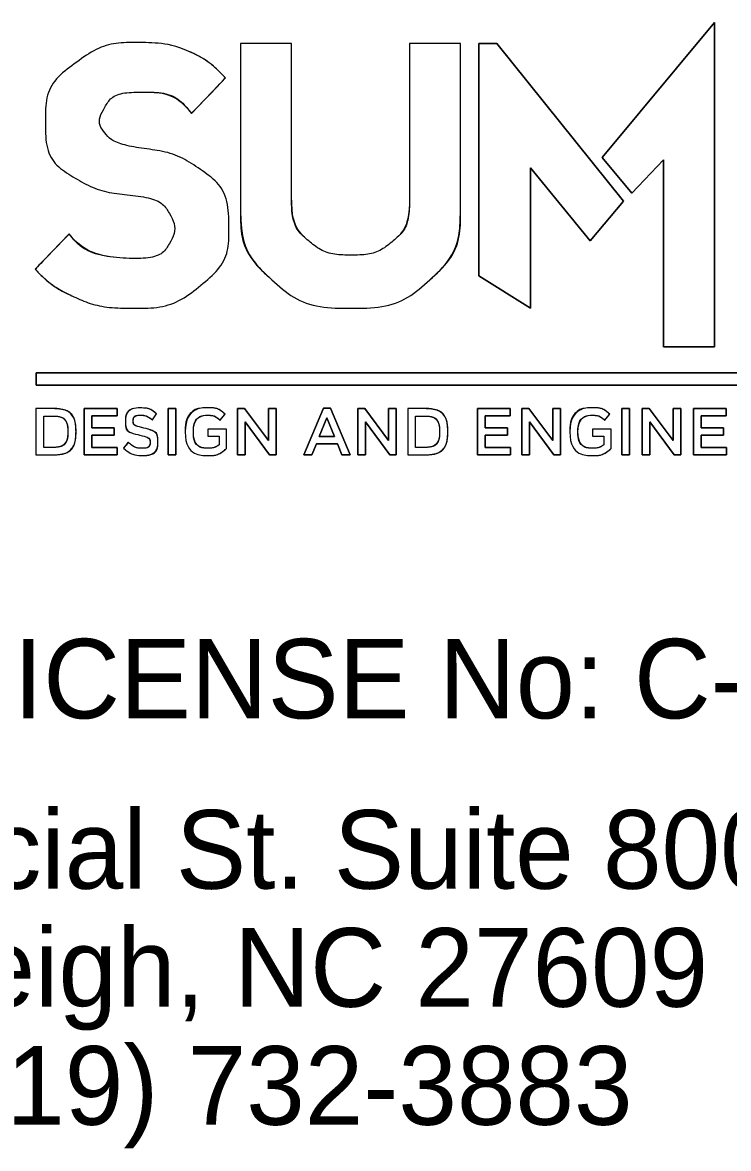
# Model space of a CAD drawing. Extents: x 1676398 to 1678098, y 1329391 to 1330491.
# Drawn here: x 1678017.5 to 1678052.2, y 1330290.2 to 1330345.6 of the extents above; entities that cross this region are included whole.
import ezdxf

# ---------------------------------------------------------------- set-up
doc = ezdxf.new("R2010")
doc.units = 0
doc.layers.add('Sheet Plan CELL', color=7, linetype='Continuous')

msp = doc.modelspace()

# ---------------------------------------------------------------- linework, layer by layer
at = {"layer": 'Sheet Plan CELL'}
for p, q in [((1678025.855, 1330341.09), (1678027.526, 1330342.832)), ((1678019.841, 1330335.167), (1678018.17, 1330333.425)), ((1678022.603, 1330325.946), (1678022.603, 1330325.94)), ((1678022.986, 1330325.975), (1678022.986, 1330325.982)), ((1678023.932, 1330326.018), (1678024.138, 1330326.319)), ((1678027.262, 1330326.001), (1678027.504, 1330326.303)), ((1678046.168, 1330326.001), (1678046.411, 1330326.303)), ((1678019.775, 1330325.437), (1678019.775, 1330325.43)), ((1678020.177, 1330325.437), (1678020.177, 1330325.443)), ((1678025.544, 1330325.437), (1678025.544, 1330325.43)), ((1678025.945, 1330325.437), (1678025.945, 1330325.443)), ((1678038.049, 1330325.437), (1678038.049, 1330325.43)), ((1678038.451, 1330325.437), (1678038.451, 1330325.443)), ((1678044.45, 1330325.437), (1678044.45, 1330325.43)), ((1678044.851, 1330325.437), (1678044.851, 1330325.443)), ((1678022.746, 1330324.918), (1678022.516, 1330324.632)), ((1678023.82, 1330324.914), (1678023.82, 1330324.908)), ((1678024.203, 1330324.947), (1678024.203, 1330324.953))]:
    msp.add_line(p, q, dxfattribs=at)
for points in [[(1678051.569, 1330345.559), (1678051.569, 1330329.619), (1678049.058, 1330329.619), (1678049.058, 1330338.813), (1678047.503, 1330337.167), (1678046.041, 1330338.914), (1678051.569, 1330345.559)], [(1678046.041, 1330338.914), (1678047.503, 1330337.167), (1678049.058, 1330338.813), (1678049.058, 1330329.619), (1678051.569, 1330329.619), (1678051.569, 1330345.559), (1678046.041, 1330338.914)], [(1678030.773, 1330336.997), (1678030.773, 1330344.521), (1678028.262, 1330344.521), (1678028.262, 1330336.3)], [(1678039.079, 1330336.3), (1678039.079, 1330344.521), (1678036.567, 1330344.521), (1678036.567, 1330336.997)], [(1678040.865, 1330344.521), (1678047.096, 1330336.768), (1678045.45, 1330334.816), (1678042.511, 1330338.409), (1678042.511, 1330331.506), (1678039.98, 1330333.11), (1678039.98, 1330344.521), (1678040.865, 1330344.521)], [(1678039.98, 1330344.521), (1678039.98, 1330333.11), (1678042.511, 1330331.506), (1678042.511, 1330338.409), (1678045.45, 1330334.816), (1678047.096, 1330336.768), (1678040.865, 1330344.521), (1678039.98, 1330344.521)], [(1678079.061, 1330327.731), (1678018.218, 1330327.731), (1678018.218, 1330328.335), (1678079.061, 1330328.335), (1678079.061, 1330327.731)], [(1678079.061, 1330328.335), (1678018.218, 1330328.335), (1678018.218, 1330327.731), (1678079.061, 1330327.731), (1678079.061, 1330328.335)], [(1678019.019, 1330326.572), (1678018.207, 1330326.572), (1678018.207, 1330324.301), (1678019.019, 1330324.301)], [(1678020.578, 1330326.572), (1678022.193, 1330326.572), (1678022.193, 1330326.215), (1678020.96, 1330326.215), (1678020.96, 1330325.625), (1678022.053, 1330325.625), (1678022.053, 1330325.268), (1678020.96, 1330325.268), (1678020.96, 1330324.658), (1678022.208, 1330324.658), (1678022.208, 1330324.301), (1678020.578, 1330324.301), (1678020.578, 1330326.572)], [(1678020.578, 1330324.301), (1678022.208, 1330324.301), (1678022.208, 1330324.658), (1678020.96, 1330324.658), (1678020.96, 1330325.268), (1678022.053, 1330325.268), (1678022.053, 1330325.625), (1678020.96, 1330325.625), (1678020.96, 1330326.215), (1678022.193, 1330326.215), (1678022.193, 1330326.572), (1678020.578, 1330326.572), (1678020.578, 1330324.301)], [(1678024.706, 1330326.572), (1678025.089, 1330326.572), (1678025.089, 1330324.301), (1678024.706, 1330324.301), (1678024.706, 1330326.572)], [(1678024.706, 1330324.301), (1678025.089, 1330324.301), (1678025.089, 1330326.572), (1678024.706, 1330326.572), (1678024.706, 1330324.301)], [(1678028.111, 1330326.572), (1678028.465, 1330326.572), (1678029.633, 1330325.002), (1678029.633, 1330326.572), (1678030.009, 1330326.572), (1678030.009, 1330324.301), (1678029.688, 1330324.301), (1678028.487, 1330325.917), (1678028.487, 1330324.301), (1678028.111, 1330324.301), (1678028.111, 1330326.572)], [(1678028.111, 1330324.301), (1678028.487, 1330324.301), (1678028.487, 1330325.917), (1678029.688, 1330324.301), (1678030.009, 1330324.301), (1678030.009, 1330326.572), (1678029.633, 1330326.572), (1678029.633, 1330325.002), (1678028.465, 1330326.572), (1678028.111, 1330326.572), (1678028.111, 1330324.301)], [(1678032.336, 1330326.589), (1678032.691, 1330326.589), (1678033.65, 1330324.301), (1678033.245, 1330324.301), (1678033.024, 1330324.849), (1678031.994, 1330324.849), (1678031.77, 1330324.301), (1678031.378, 1330324.301), (1678032.336, 1330326.589)], [(1678031.378, 1330324.301), (1678031.77, 1330324.301), (1678031.994, 1330324.849), (1678033.024, 1330324.849), (1678033.245, 1330324.301), (1678033.65, 1330324.301), (1678032.691, 1330326.589), (1678032.336, 1330326.589), (1678031.378, 1330324.301)], [(1678034.023, 1330326.572), (1678034.378, 1330326.572), (1678035.544, 1330325.002), (1678035.544, 1330326.572), (1678035.921, 1330326.572), (1678035.921, 1330324.301), (1678035.601, 1330324.301), (1678034.399, 1330325.917), (1678034.399, 1330324.301), (1678034.023, 1330324.301), (1678034.023, 1330326.572)], [(1678034.023, 1330324.301), (1678034.399, 1330324.301), (1678034.399, 1330325.917), (1678035.601, 1330324.301), (1678035.921, 1330324.301), (1678035.921, 1330326.572), (1678035.544, 1330326.572), (1678035.544, 1330325.002), (1678034.378, 1330326.572), (1678034.023, 1330326.572), (1678034.023, 1330324.301)], [(1678037.293, 1330326.572), (1678036.481, 1330326.572), (1678036.481, 1330324.301), (1678037.293, 1330324.301)], [(1678039.91, 1330326.572), (1678041.525, 1330326.572), (1678041.525, 1330326.215), (1678040.293, 1330326.215), (1678040.293, 1330325.625), (1678041.385, 1330325.625), (1678041.385, 1330325.268), (1678040.293, 1330325.268), (1678040.293, 1330324.658), (1678041.541, 1330324.658), (1678041.541, 1330324.301), (1678039.91, 1330324.301), (1678039.91, 1330326.572)], [(1678039.91, 1330324.301), (1678041.541, 1330324.301), (1678041.541, 1330324.658), (1678040.293, 1330324.658), (1678040.293, 1330325.268), (1678041.385, 1330325.268), (1678041.385, 1330325.625), (1678040.293, 1330325.625), (1678040.293, 1330326.215), (1678041.525, 1330326.215), (1678041.525, 1330326.572), (1678039.91, 1330326.572), (1678039.91, 1330324.301)], [(1678042.088, 1330326.572), (1678042.443, 1330326.572), (1678043.61, 1330325.002), (1678043.61, 1330326.572), (1678043.986, 1330326.572), (1678043.986, 1330324.301), (1678043.666, 1330324.301), (1678042.464, 1330325.917), (1678042.464, 1330324.301), (1678042.088, 1330324.301), (1678042.088, 1330326.572)], [(1678042.088, 1330324.301), (1678042.464, 1330324.301), (1678042.464, 1330325.917), (1678043.666, 1330324.301), (1678043.986, 1330324.301), (1678043.986, 1330326.572), (1678043.61, 1330326.572), (1678043.61, 1330325.002), (1678042.443, 1330326.572), (1678042.088, 1330326.572), (1678042.088, 1330324.301)], [(1678047.007, 1330326.572), (1678047.39, 1330326.572), (1678047.39, 1330324.301), (1678047.007, 1330324.301), (1678047.007, 1330326.572)], [(1678047.007, 1330324.301), (1678047.39, 1330324.301), (1678047.39, 1330326.572), (1678047.007, 1330326.572), (1678047.007, 1330324.301)], [(1678048.003, 1330326.572), (1678048.358, 1330326.572), (1678049.525, 1330325.002), (1678049.525, 1330326.572), (1678049.902, 1330326.572), (1678049.902, 1330324.301), (1678049.581, 1330324.301), (1678048.38, 1330325.917), (1678048.38, 1330324.301), (1678048.003, 1330324.301), (1678048.003, 1330326.572)], [(1678048.003, 1330324.301), (1678048.38, 1330324.301), (1678048.38, 1330325.917), (1678049.581, 1330324.301), (1678049.902, 1330324.301), (1678049.902, 1330326.572), (1678049.525, 1330326.572), (1678049.525, 1330325.002), (1678048.358, 1330326.572), (1678048.003, 1330326.572), (1678048.003, 1330324.301)], [(1678050.523, 1330326.572), (1678052.139, 1330326.572), (1678052.139, 1330326.215), (1678050.906, 1330326.215), (1678050.906, 1330325.625), (1678051.999, 1330325.625), (1678051.999, 1330325.268), (1678050.906, 1330325.268), (1678050.906, 1330324.658), (1678052.154, 1330324.658), (1678052.154, 1330324.301), (1678050.523, 1330324.301), (1678050.523, 1330326.572)], [(1678050.523, 1330324.301), (1678052.154, 1330324.301), (1678052.154, 1330324.658), (1678050.906, 1330324.658), (1678050.906, 1330325.268), (1678051.999, 1330325.268), (1678051.999, 1330325.625), (1678050.906, 1330325.625), (1678050.906, 1330326.215), (1678052.139, 1330326.215), (1678052.139, 1330326.572), (1678050.523, 1330326.572), (1678050.523, 1330324.301)], [(1678019.019, 1330324.664), (1678018.59, 1330324.664), (1678018.59, 1330326.209), (1678019.019, 1330326.209)], [(1678032.884, 1330325.203), (1678032.508, 1330326.112), (1678032.134, 1330325.203), (1678032.884, 1330325.203)], [(1678032.134, 1330325.203), (1678032.508, 1330326.112), (1678032.884, 1330325.203), (1678032.134, 1330325.203)], [(1678037.293, 1330324.664), (1678036.864, 1330324.664), (1678036.864, 1330326.209), (1678037.293, 1330326.209)], [(1678027.582, 1330324.616), (1678027.582, 1330325.57), (1678026.655, 1330325.57), (1678026.655, 1330325.223), (1678027.212, 1330325.223), (1678027.212, 1330324.797)], [(1678046.488, 1330324.616), (1678046.488, 1330325.57), (1678045.561, 1330325.57), (1678045.561, 1330325.223), (1678046.118, 1330325.223), (1678046.118, 1330324.797)]]:
    msp.add_lwpolyline(points, dxfattribs=at)
for points, degree in [([(1678025.729, 1330344.138), (1678026.37, 1330343.848), (1678026.969, 1330343.413), (1678027.526, 1330342.832), (1678027.526, 1330342.832), (1678025.855, 1330341.09), (1678025.855, 1330341.09), (1678025.298, 1330341.787), (1678024.519, 1330342.135), (1678023.515, 1330342.135), (1678022.514, 1330342.135), (1678021.873, 1330341.888), (1678021.594, 1330341.394), (1678021.316, 1330340.901), (1678021.316, 1330340.481), (1678021.594, 1330340.132), (1678021.873, 1330339.783), (1678022.514, 1330339.522), (1678023.515, 1330339.348), (1678024.574, 1330339.233), (1678025.535, 1330338.869), (1678026.398, 1330338.259), (1678027.261, 1330337.65), (1678027.692, 1330336.678), (1678027.692, 1330335.342), (1678027.692, 1330334.296), (1678027.232, 1330333.397), (1678026.31, 1330332.642), (1678025.389, 1330331.887), (1678024.315, 1330331.509), (1678023.089, 1330331.509), (1678021.926, 1330331.509), (1678020.954, 1330331.683), (1678020.174, 1330332.032), (1678019.394, 1330332.381), (1678018.726, 1330332.845), (1678018.17, 1330333.425), (1678018.17, 1330333.425), (1678019.841, 1330335.167), (1678019.841, 1330335.167), (1678020.397, 1330334.471), (1678021.344, 1330334.064), (1678022.681, 1330333.948), (1678023.795, 1330333.948), (1678024.489, 1330334.195), (1678024.765, 1330334.689), (1678025.04, 1330335.182), (1678025.04, 1330335.675), (1678024.765, 1330336.169), (1678024.489, 1330336.663), (1678023.795, 1330336.967), (1678022.681, 1330337.084), (1678021.678, 1330337.2), (1678020.759, 1330337.519), (1678019.924, 1330338.042), (1678019.089, 1330338.565), (1678018.67, 1330339.464), (1678018.67, 1330340.742), (1678018.67, 1330341.897), (1678019.145, 1330342.824), (1678020.095, 1330343.524), (1678021.044, 1330344.225), (1678022.02, 1330344.574), (1678023.023, 1330344.574), (1678024.187, 1330344.574), (1678025.089, 1330344.43), (1678025.729, 1330344.138)], 3), ([(1678025.729, 1330344.138), (1678025.089, 1330344.43), (1678024.187, 1330344.574), (1678023.023, 1330344.574), (1678022.02, 1330344.574), (1678021.044, 1330344.225), (1678020.095, 1330343.524), (1678019.145, 1330342.824), (1678018.67, 1330341.897), (1678018.67, 1330340.742), (1678018.67, 1330339.464), (1678019.089, 1330338.565), (1678019.924, 1330338.042), (1678020.759, 1330337.519), (1678021.678, 1330337.2), (1678022.681, 1330337.084), (1678023.795, 1330336.967), (1678024.489, 1330336.663), (1678024.765, 1330336.169), (1678025.04, 1330335.675), (1678025.04, 1330335.182), (1678024.765, 1330334.689), (1678024.489, 1330334.195), (1678023.795, 1330333.948), (1678022.681, 1330333.948), (1678021.344, 1330334.064), (1678020.397, 1330334.471), (1678019.841, 1330335.167)], 3), ([(1678027.526, 1330342.832), (1678026.969, 1330343.413), (1678026.37, 1330343.848), (1678025.729, 1330344.138)], 2), ([(1678030.773, 1330344.521), (1678030.773, 1330344.521), (1678030.773, 1330336.997), (1678030.773, 1330336.997), (1678030.773, 1330336.009), (1678031.057, 1330335.284), (1678031.614, 1330334.819), (1678032.172, 1330334.354), (1678032.871, 1330334.122), (1678033.706, 1330334.122), (1678034.542, 1330334.122), (1678035.207, 1330334.354), (1678035.764, 1330334.819), (1678036.32, 1330335.284), (1678036.567, 1330336.009), (1678036.567, 1330336.997), (1678036.567, 1330336.997), (1678036.567, 1330344.521), (1678036.567, 1330344.521), (1678036.567, 1330344.521), (1678039.079, 1330344.521), (1678039.079, 1330344.521), (1678039.079, 1330344.521), (1678039.079, 1330336.3), (1678039.079, 1330336.3), (1678039.079, 1330334.964), (1678038.594, 1330333.832), (1678037.563, 1330332.903), (1678036.533, 1330331.975), (1678035.254, 1330331.509), (1678033.694, 1330331.509), (1678032.135, 1330331.509), (1678030.838, 1330331.975), (1678029.809, 1330332.903), (1678028.778, 1330333.832), (1678028.262, 1330334.964), (1678028.262, 1330336.3), (1678028.262, 1330336.3), (1678028.262, 1330344.521), (1678028.262, 1330344.521), (1678028.262, 1330344.521), (1678030.773, 1330344.521), (1678030.773, 1330344.521)], 3), ([(1678018.17, 1330333.425), (1678018.726, 1330332.845), (1678019.394, 1330332.381), (1678020.174, 1330332.032), (1678020.954, 1330331.683), (1678021.926, 1330331.509), (1678023.089, 1330331.509), (1678024.315, 1330331.509), (1678025.389, 1330331.887), (1678026.31, 1330332.642), (1678027.232, 1330333.397), (1678027.692, 1330334.296), (1678027.692, 1330335.342), (1678027.692, 1330336.678), (1678027.261, 1330337.65), (1678026.398, 1330338.259), (1678025.535, 1330338.869), (1678024.574, 1330339.233), (1678023.515, 1330339.348), (1678022.514, 1330339.522), (1678021.873, 1330339.783), (1678021.594, 1330340.132), (1678021.316, 1330340.481), (1678021.316, 1330340.901), (1678021.594, 1330341.394), (1678021.873, 1330341.888), (1678022.514, 1330342.135), (1678023.515, 1330342.135), (1678024.519, 1330342.135), (1678025.298, 1330341.787), (1678025.855, 1330341.09)], 3), ([(1678036.567, 1330336.997), (1678036.567, 1330336.009), (1678036.32, 1330335.284), (1678035.764, 1330334.819), (1678035.207, 1330334.354), (1678034.542, 1330334.122), (1678033.706, 1330334.122), (1678032.871, 1330334.122), (1678032.172, 1330334.354), (1678031.614, 1330334.819), (1678031.057, 1330335.284), (1678030.773, 1330336.009), (1678030.773, 1330336.997)], 3), ([(1678028.262, 1330336.3), (1678028.262, 1330334.964), (1678028.778, 1330333.832), (1678029.809, 1330332.903), (1678030.838, 1330331.975), (1678032.135, 1330331.509), (1678033.694, 1330331.509), (1678035.254, 1330331.509), (1678036.533, 1330331.975), (1678037.563, 1330332.903), (1678038.594, 1330333.832), (1678039.079, 1330334.964), (1678039.079, 1330336.3)], 3), ([(1678018.207, 1330326.572), (1678018.207, 1330326.572), (1678019.019, 1330326.572), (1678019.019, 1330326.572), (1678019.704, 1330326.572), (1678020.177, 1330326.082), (1678020.177, 1330325.443), (1678020.177, 1330325.443), (1678020.177, 1330325.437), (1678020.177, 1330325.437), (1678020.177, 1330324.797), (1678019.704, 1330324.301), (1678019.019, 1330324.301), (1678019.019, 1330324.301), (1678018.207, 1330324.301), (1678018.207, 1330324.301), (1678018.207, 1330324.301), (1678018.207, 1330326.572), (1678018.207, 1330326.572)], 3), ([(1678020.177, 1330325.443), (1678020.177, 1330326.082), (1678019.704, 1330326.572), (1678019.019, 1330326.572)], 2), ([(1678022.516, 1330324.632), (1678022.516, 1330324.632), (1678022.746, 1330324.918), (1678022.746, 1330324.918), (1678022.955, 1330324.729), (1678023.166, 1330324.622), (1678023.434, 1330324.622), (1678023.671, 1330324.622), (1678023.82, 1330324.739), (1678023.82, 1330324.908), (1678023.82, 1330324.908), (1678023.82, 1330324.914), (1678023.82, 1330324.914), (1678023.82, 1330325.076), (1678023.733, 1330325.164), (1678023.328, 1330325.262), (1678022.865, 1330325.378), (1678022.603, 1330325.521), (1678022.603, 1330325.94), (1678022.603, 1330325.94), (1678022.603, 1330325.946), (1678022.603, 1330325.946), (1678022.603, 1330326.336), (1678022.914, 1330326.605), (1678023.347, 1330326.605), (1678023.665, 1330326.605), (1678023.917, 1330326.504), (1678024.138, 1330326.319), (1678024.138, 1330326.319), (1678023.932, 1330326.018), (1678023.932, 1330326.018), (1678023.736, 1330326.17), (1678023.54, 1330326.251), (1678023.341, 1330326.251), (1678023.117, 1330326.251), (1678022.986, 1330326.131), (1678022.986, 1330325.982), (1678022.986, 1330325.982), (1678022.986, 1330325.975), (1678022.986, 1330325.975), (1678022.986, 1330325.8), (1678023.086, 1330325.722), (1678023.506, 1330325.618), (1678023.966, 1330325.502), (1678024.203, 1330325.33), (1678024.203, 1330324.953), (1678024.203, 1330324.953), (1678024.203, 1330324.947), (1678024.203, 1330324.947), (1678024.203, 1330324.522), (1678023.882, 1330324.269), (1678023.425, 1330324.269), (1678023.092, 1330324.269), (1678022.778, 1330324.389), (1678022.516, 1330324.632)], 3), ([(1678024.138, 1330326.319), (1678023.917, 1330326.504), (1678023.665, 1330326.605), (1678023.347, 1330326.605), (1678022.914, 1330326.605), (1678022.603, 1330326.336), (1678022.603, 1330325.946)], 3), ([(1678025.544, 1330325.43), (1678025.544, 1330325.43), (1678025.544, 1330325.437), (1678025.544, 1330325.437), (1678025.544, 1330326.073), (1678026.01, 1330326.611), (1678026.667, 1330326.611), (1678027.047, 1330326.611), (1678027.28, 1330326.501), (1678027.504, 1330326.303), (1678027.504, 1330326.303), (1678027.262, 1330326.001), (1678027.262, 1330326.001), (1678027.093, 1330326.151), (1678026.929, 1330326.245), (1678026.652, 1330326.245), (1678026.25, 1330326.245), (1678025.945, 1330325.878), (1678025.945, 1330325.443), (1678025.945, 1330325.443), (1678025.945, 1330325.437), (1678025.945, 1330325.437), (1678025.945, 1330324.969), (1678026.241, 1330324.626), (1678026.686, 1330324.626), (1678026.891, 1330324.626), (1678027.078, 1330324.694), (1678027.212, 1330324.797), (1678027.212, 1330324.797), (1678027.212, 1330325.223), (1678027.212, 1330325.223), (1678027.212, 1330325.223), (1678026.655, 1330325.223), (1678026.655, 1330325.223), (1678026.655, 1330325.223), (1678026.655, 1330325.57), (1678026.655, 1330325.57), (1678026.655, 1330325.57), (1678027.582, 1330325.57), (1678027.582, 1330325.57), (1678027.582, 1330325.57), (1678027.582, 1330324.616), (1678027.582, 1330324.616), (1678027.367, 1330324.424), (1678027.059, 1330324.262), (1678026.673, 1330324.262), (1678025.992, 1330324.262), (1678025.544, 1330324.768), (1678025.544, 1330325.43)], 3), ([(1678027.504, 1330326.303), (1678027.28, 1330326.501), (1678027.047, 1330326.611), (1678026.667, 1330326.611), (1678026.01, 1330326.611), (1678025.544, 1330326.073), (1678025.544, 1330325.437)], 3), ([(1678036.481, 1330326.572), (1678036.481, 1330326.572), (1678037.293, 1330326.572), (1678037.293, 1330326.572), (1678037.978, 1330326.572), (1678038.451, 1330326.082), (1678038.451, 1330325.443), (1678038.451, 1330325.443), (1678038.451, 1330325.437), (1678038.451, 1330325.437), (1678038.451, 1330324.797), (1678037.978, 1330324.301), (1678037.293, 1330324.301), (1678037.293, 1330324.301), (1678036.481, 1330324.301), (1678036.481, 1330324.301), (1678036.481, 1330324.301), (1678036.481, 1330326.572), (1678036.481, 1330326.572)], 3), ([(1678038.451, 1330325.443), (1678038.451, 1330326.082), (1678037.978, 1330326.572), (1678037.293, 1330326.572)], 2), ([(1678044.45, 1330325.43), (1678044.45, 1330325.43), (1678044.45, 1330325.437), (1678044.45, 1330325.437), (1678044.45, 1330326.073), (1678044.917, 1330326.611), (1678045.573, 1330326.611), (1678045.953, 1330326.611), (1678046.186, 1330326.501), (1678046.411, 1330326.303), (1678046.411, 1330326.303), (1678046.168, 1330326.001), (1678046.168, 1330326.001), (1678046, 1330326.151), (1678045.835, 1330326.245), (1678045.557, 1330326.245), (1678045.156, 1330326.245), (1678044.851, 1330325.878), (1678044.851, 1330325.443), (1678044.851, 1330325.443), (1678044.851, 1330325.437), (1678044.851, 1330325.437), (1678044.851, 1330324.969), (1678045.147, 1330324.626), (1678045.592, 1330324.626), (1678045.797, 1330324.626), (1678045.984, 1330324.694), (1678046.118, 1330324.797), (1678046.118, 1330324.797), (1678046.118, 1330325.223), (1678046.118, 1330325.223), (1678046.118, 1330325.223), (1678045.561, 1330325.223), (1678045.561, 1330325.223), (1678045.561, 1330325.223), (1678045.561, 1330325.57), (1678045.561, 1330325.57), (1678045.561, 1330325.57), (1678046.488, 1330325.57), (1678046.488, 1330325.57), (1678046.488, 1330325.57), (1678046.488, 1330324.616), (1678046.488, 1330324.616), (1678046.274, 1330324.424), (1678045.965, 1330324.262), (1678045.58, 1330324.262), (1678044.898, 1330324.262), (1678044.45, 1330324.768), (1678044.45, 1330325.43)], 3), ([(1678046.411, 1330326.303), (1678046.186, 1330326.501), (1678045.953, 1330326.611), (1678045.573, 1330326.611), (1678044.917, 1330326.611), (1678044.45, 1330326.073), (1678044.45, 1330325.437)], 3), ([(1678018.59, 1330326.209), (1678018.59, 1330326.209), (1678018.59, 1330324.664), (1678018.59, 1330324.664), (1678018.59, 1330324.664), (1678019.019, 1330324.664), (1678019.019, 1330324.664), (1678019.476, 1330324.664), (1678019.775, 1330324.986), (1678019.775, 1330325.43), (1678019.775, 1330325.43), (1678019.775, 1330325.437), (1678019.775, 1330325.437), (1678019.775, 1330325.881), (1678019.476, 1330326.209), (1678019.019, 1330326.209), (1678019.019, 1330326.209), (1678018.59, 1330326.209), (1678018.59, 1330326.209)], 3), ([(1678019.019, 1330326.209), (1678019.476, 1330326.209), (1678019.775, 1330325.881), (1678019.775, 1330325.437)], 2), ([(1678022.603, 1330325.94), (1678022.603, 1330325.521), (1678022.865, 1330325.378), (1678023.328, 1330325.262), (1678023.733, 1330325.164), (1678023.82, 1330325.076), (1678023.82, 1330324.914)], 3), ([(1678022.986, 1330325.982), (1678022.986, 1330326.131), (1678023.117, 1330326.251), (1678023.341, 1330326.251), (1678023.54, 1330326.251), (1678023.736, 1330326.17), (1678023.932, 1330326.018)], 3), ([(1678024.203, 1330324.953), (1678024.203, 1330325.33), (1678023.966, 1330325.502), (1678023.506, 1330325.618), (1678023.086, 1330325.722), (1678022.986, 1330325.8), (1678022.986, 1330325.975)], 3), ([(1678025.945, 1330325.443), (1678025.945, 1330325.878), (1678026.25, 1330326.245), (1678026.652, 1330326.245), (1678026.929, 1330326.245), (1678027.093, 1330326.151), (1678027.262, 1330326.001)], 3), ([(1678036.864, 1330326.209), (1678036.864, 1330326.209), (1678036.864, 1330324.664), (1678036.864, 1330324.664), (1678036.864, 1330324.664), (1678037.293, 1330324.664), (1678037.293, 1330324.664), (1678037.751, 1330324.664), (1678038.049, 1330324.986), (1678038.049, 1330325.43), (1678038.049, 1330325.43), (1678038.049, 1330325.437), (1678038.049, 1330325.437), (1678038.049, 1330325.881), (1678037.751, 1330326.209), (1678037.293, 1330326.209), (1678037.293, 1330326.209), (1678036.864, 1330326.209), (1678036.864, 1330326.209)], 3), ([(1678037.293, 1330326.209), (1678037.751, 1330326.209), (1678038.049, 1330325.881), (1678038.049, 1330325.437)], 2), ([(1678044.851, 1330325.443), (1678044.851, 1330325.878), (1678045.156, 1330326.245), (1678045.557, 1330326.245), (1678045.835, 1330326.245), (1678046, 1330326.151), (1678046.168, 1330326.001)], 3), ([(1678019.019, 1330324.301), (1678019.704, 1330324.301), (1678020.177, 1330324.797), (1678020.177, 1330325.437)], 2), ([(1678019.775, 1330325.43), (1678019.775, 1330324.986), (1678019.476, 1330324.664), (1678019.019, 1330324.664)], 2), ([(1678025.544, 1330325.43), (1678025.544, 1330324.768), (1678025.992, 1330324.262), (1678026.673, 1330324.262), (1678027.059, 1330324.262), (1678027.367, 1330324.424), (1678027.582, 1330324.616)], 3), ([(1678027.212, 1330324.797), (1678027.078, 1330324.694), (1678026.891, 1330324.626), (1678026.686, 1330324.626), (1678026.241, 1330324.626), (1678025.945, 1330324.969), (1678025.945, 1330325.437)], 3), ([(1678037.293, 1330324.301), (1678037.978, 1330324.301), (1678038.451, 1330324.797), (1678038.451, 1330325.437)], 2), ([(1678038.049, 1330325.43), (1678038.049, 1330324.986), (1678037.751, 1330324.664), (1678037.293, 1330324.664)], 2), ([(1678044.45, 1330325.43), (1678044.45, 1330324.768), (1678044.898, 1330324.262), (1678045.58, 1330324.262), (1678045.965, 1330324.262), (1678046.274, 1330324.424), (1678046.488, 1330324.616)], 3), ([(1678046.118, 1330324.797), (1678045.984, 1330324.694), (1678045.797, 1330324.626), (1678045.592, 1330324.626), (1678045.147, 1330324.626), (1678044.851, 1330324.969), (1678044.851, 1330325.437)], 3), ([(1678022.516, 1330324.632), (1678022.778, 1330324.389), (1678023.092, 1330324.269), (1678023.425, 1330324.269), (1678023.882, 1330324.269), (1678024.203, 1330324.522), (1678024.203, 1330324.947)], 3), ([(1678023.82, 1330324.908), (1678023.82, 1330324.739), (1678023.671, 1330324.622), (1678023.434, 1330324.622), (1678023.166, 1330324.622), (1678022.955, 1330324.729), (1678022.746, 1330324.918)], 3)]:
    msp.add_open_spline(points, degree=degree, dxfattribs=at)

# ---------------------------------------------------------------- texts
for s, height, p in [('NC FIRM LICENSE No: C-5176', 3.90762, (1677990.987, 1330311.342)), ('1000 Social St. Suite 800.', 3.86958, (1677996.606, 1330302.964)), ('Raleigh, NC 27609', 3.86958, (1678007.525, 1330297.16)), ('(919) 732-3883', 3.86958, (1678012.148, 1330291.356))]:
    msp.add_text(s, height=height, rotation=360, dxfattribs=at).set_placement(p)

doc.saveas('drawing.dxf')
